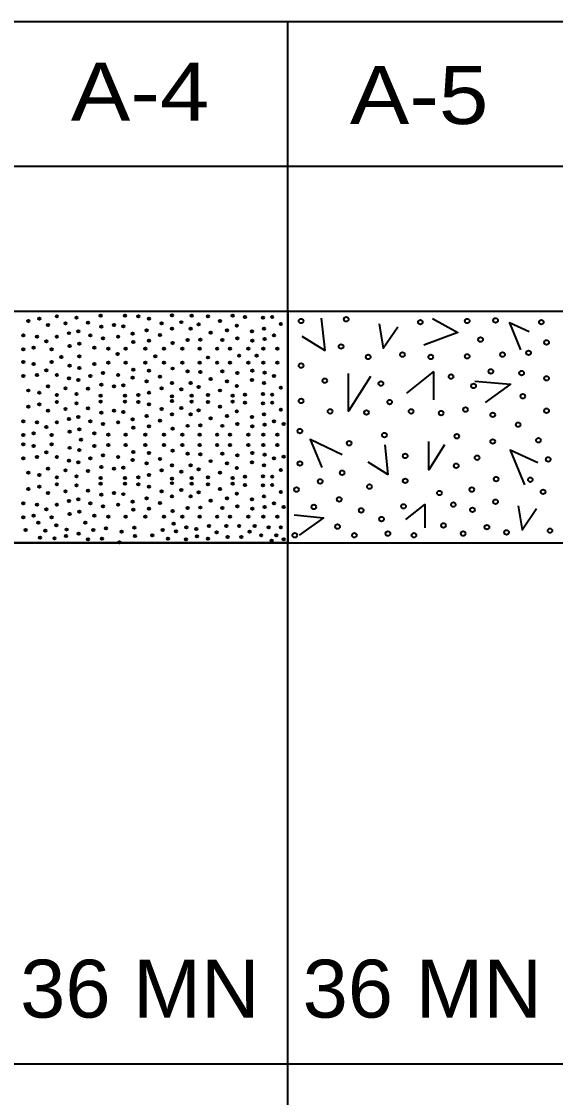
# Model space of a CAD drawing. Extents: x 2137492.6 to 2137529.1, y 2137475.8 to 2137563.
# Drawn here: x 2137497.407 to 2137498.33, y 2137553.765 to 2137555.623 of the extents above; entities that cross this region are included whole.
import ezdxf
from ezdxf.enums import TextEntityAlignment as Align

# ---------------------------------------------------------------- set-up
doc = ezdxf.new("R2010")
doc.units = 0
doc.header["$LTSCALE"] = 0.04
doc.layers.add('1', color=7, linetype='Continuous', lineweight=35)

msp = doc.modelspace()

# ---------------------------------------------------------------- linework, layer by layer
at = {"layer": '1'}
for p, q in [((2137493.171, 2137555.623), (2137501.871, 2137555.623)), ((2137497.867, 2137552.923), (2137497.867, 2137555.623)), ((2137494.121, 2137555.373), (2137499.271, 2137555.373)), ((2137493.171, 2137555.123), (2137501.871, 2137555.123)), ((2137493.171, 2137554.723), (2137501.871, 2137554.723)), ((2137493.171, 2137553.823), (2137501.871, 2137553.823))]:
    msp.add_line(p, q, dxfattribs=at)
msp.add_lwpolyline([(2137497.371, 2137555.123), (2137497.867, 2137555.123), (2137497.867, 2137554.723), (2137497.371, 2137554.723)], close=True, dxfattribs=at)
for points in [[(2137497.925, 2137555.111), (2137497.931, 2137555.055), (2137497.892, 2137555.079)], [(2137498.117, 2137555.11), (2137498.161, 2137555.086), (2137498.102, 2137555.064)], [(2137498.025, 2137555.101), (2137498.032, 2137555.059), (2137498.057, 2137555.096)], [(2137498.284, 2137555.087), (2137498.25, 2137555.103), (2137498.269, 2137555.056)], [(2137498.01, 2137555.01), (2137497.972, 2137554.95), (2137497.972, 2137555.015)], [(2137498.073, 2137554.981), (2137498.119, 2137555.018), (2137498.119, 2137554.97)], [(2137498.19, 2137555.002), (2137498.252, 2137554.997), (2137498.208, 2137554.965)], [(2137497.961, 2137554.875), (2137497.906, 2137554.901), (2137497.926, 2137554.853)], [(2137498.035, 2137554.892), (2137498.04, 2137554.841), (2137498.006, 2137554.862)], [(2137498.138, 2137554.892), (2137498.111, 2137554.849), (2137498.111, 2137554.898)], [(2137498.299, 2137554.861), (2137498.251, 2137554.883), (2137498.276, 2137554.823)], [(2137498.071, 2137554.763), (2137498.104, 2137554.789), (2137498.104, 2137554.749)], [(2137498.265, 2137554.787), (2137498.272, 2137554.745), (2137498.297, 2137554.782)], [(2137497.878, 2137554.771), (2137497.929, 2137554.766), (2137497.887, 2137554.736)]]:
    msp.add_lwpolyline(points, dxfattribs=at)
for centre, radius in [((2137497.41906, 2137555.10586), 0.002), ((2137497.43806, 2137555.10986), 0.002), ((2137497.46806, 2137555.11386), 0.002), ((2137497.50206, 2137555.11186), 0.002), ((2137497.54406, 2137555.11486), 0.002), ((2137497.58606, 2137555.11486), 0.002), ((2137497.60906, 2137555.11386), 0.002), ((2137497.62706, 2137555.10986), 0.002), ((2137497.66706, 2137555.11586), 0.002), ((2137497.68306, 2137555.10386), 0.002), ((2137497.70106, 2137555.11486), 0.002), ((2137497.72906, 2137555.11386), 0.002), ((2137497.75006, 2137555.10586), 0.002), ((2137497.77206, 2137555.11486), 0.002), ((2137497.79306, 2137555.11286), 0.002), ((2137497.82406, 2137555.11186), 0.002), ((2137497.84006, 2137555.11286), 0.002), ((2137497.89006, 2137555.10586), 0.004), ((2137497.96806, 2137555.10886), 0.004), ((2137498.09606, 2137555.10386), 0.004), ((2137498.17706, 2137555.10586), 0.004), ((2137498.22606, 2137555.10686), 0.004), ((2137498.30506, 2137555.10386), 0.004), ((2137497.45306, 2137555.09886), 0.002), ((2137497.48306, 2137555.10186), 0.002), ((2137497.50506, 2137555.08786), 0.002), ((2137497.52206, 2137555.10286), 0.002), ((2137497.54506, 2137555.09586), 0.002), ((2137497.56706, 2137555.09886), 0.002), ((2137497.58306, 2137555.09686), 0.002), ((2137497.62306, 2137555.08986), 0.002), ((2137497.64906, 2137555.10186), 0.002), ((2137497.66706, 2137555.09286), 0.002), ((2137497.69906, 2137555.09286), 0.002), ((2137497.71306, 2137555.09986), 0.002), ((2137497.73406, 2137555.08586), 0.002), ((2137497.76206, 2137555.08986), 0.002), ((2137497.77906, 2137555.09786), 0.002), ((2137497.80506, 2137555.08786), 0.002), ((2137497.82606, 2137555.09286), 0.002), ((2137497.85506, 2137555.10086), 0.002), ((2137497.41006, 2137555.08086), 0.002), ((2137497.43406, 2137555.07886), 0.002), ((2137497.45006, 2137555.07086), 0.002), ((2137497.46806, 2137555.07886), 0.002), ((2137497.48906, 2137555.08486), 0.002), ((2137497.50706, 2137555.06686), 0.002), ((2137497.52606, 2137555.08086), 0.002), ((2137497.54806, 2137555.07586), 0.002), ((2137497.57406, 2137555.07886), 0.002), ((2137497.59906, 2137555.08386), 0.002), ((2137497.60006, 2137555.06986), 0.002), ((2137497.62706, 2137555.07186), 0.002), ((2137497.64606, 2137555.08186), 0.002), ((2137497.66806, 2137555.06786), 0.002), ((2137497.69406, 2137555.07286), 0.002), ((2137497.71606, 2137555.07386), 0.002), ((2137497.75406, 2137555.07286), 0.002), ((2137497.78006, 2137555.07586), 0.002), ((2137497.80606, 2137555.07186), 0.002), ((2137497.82706, 2137555.07486), 0.002), ((2137497.84306, 2137555.08086), 0.002), ((2137498.20006, 2137555.07386), 0.004), ((2137498.31406, 2137555.06886), 0.004), ((2137497.41006, 2137555.05686), 0.002), ((2137497.42806, 2137555.05986), 0.002), ((2137497.45906, 2137555.05686), 0.002), ((2137497.49006, 2137555.06286), 0.002), ((2137497.53306, 2137555.05986), 0.002), ((2137497.55706, 2137555.05786), 0.002), ((2137497.57306, 2137555.04886), 0.002), ((2137497.58706, 2137555.05786), 0.002), ((2137497.62106, 2137555.05786), 0.002), ((2137497.65306, 2137555.05786), 0.002), ((2137497.68506, 2137555.05786), 0.002), ((2137497.71506, 2137555.05786), 0.002), ((2137497.74506, 2137555.05786), 0.002), ((2137497.76706, 2137555.05786), 0.002), ((2137497.79906, 2137555.05786), 0.002), ((2137497.82506, 2137555.05786), 0.002), ((2137497.84906, 2137555.05786), 0.002), ((2137497.95906, 2137555.06186), 0.004), ((2137498.06506, 2137555.04786), 0.004), ((2137498.23806, 2137555.04786), 0.004), ((2137498.28306, 2137555.05086), 0.004), ((2137497.41006, 2137555.03486), 0.002), ((2137497.42806, 2137555.03186), 0.002), ((2137497.45906, 2137555.03486), 0.002), ((2137497.47606, 2137555.04386), 0.002), ((2137497.50706, 2137555.04486), 0.002), ((2137497.53306, 2137555.03186), 0.002), ((2137497.55706, 2137555.03386), 0.002), ((2137497.58706, 2137555.03386), 0.002), ((2137497.62106, 2137555.03386), 0.002), ((2137497.63806, 2137555.04486), 0.002), ((2137497.65306, 2137555.03386), 0.002), ((2137497.68506, 2137555.03386), 0.002), ((2137497.71506, 2137555.03386), 0.002), ((2137497.72906, 2137555.04286), 0.002), ((2137497.74506, 2137555.03386), 0.002), ((2137497.76706, 2137555.03386), 0.002), ((2137497.78306, 2137555.04586), 0.002), ((2137497.79906, 2137555.03386), 0.002), ((2137497.81306, 2137555.04586), 0.002), ((2137497.82506, 2137555.03386), 0.002), ((2137497.84906, 2137555.03386), 0.002), ((2137497.89006, 2137555.02886), 0.004), ((2137498.00606, 2137555.04386), 0.004), ((2137498.11406, 2137555.04386), 0.004), ((2137498.17706, 2137555.04486), 0.004), ((2137497.41006, 2137555.01086), 0.002), ((2137497.43406, 2137555.01286), 0.002), ((2137497.45006, 2137555.02086), 0.002), ((2137497.46806, 2137555.01286), 0.002), ((2137497.49006, 2137555.02886), 0.002), ((2137497.50706, 2137555.02486), 0.002), ((2137497.52606, 2137555.01086), 0.002), ((2137497.54806, 2137555.01586), 0.002), ((2137497.57406, 2137555.01286), 0.002), ((2137497.60006, 2137555.02186), 0.002), ((2137497.62706, 2137555.01986), 0.002), ((2137497.66806, 2137555.02386), 0.002), ((2137497.69406, 2137555.01886), 0.002), ((2137497.71606, 2137555.01786), 0.002), ((2137497.75406, 2137555.01886), 0.002), ((2137497.78006, 2137555.01586), 0.002), ((2137497.80606, 2137555.01986), 0.002), ((2137497.82706, 2137555.01686), 0.002), ((2137497.84306, 2137555.01086), 0.002), ((2137498.14906, 2137555.00986), 0.004), ((2137498.21806, 2137555.01886), 0.004), ((2137498.27106, 2137555.01586), 0.004), ((2137497.45306, 2137554.99286), 0.002), ((2137497.48906, 2137555.00686), 0.002), ((2137497.50506, 2137555.00386), 0.002), ((2137497.54506, 2137554.99586), 0.002), ((2137497.56706, 2137554.99286), 0.002), ((2137497.58306, 2137554.99486), 0.002), ((2137497.59906, 2137555.00786), 0.002), ((2137497.62306, 2137555.00186), 0.002), ((2137497.64606, 2137555.00986), 0.002), ((2137497.66706, 2137554.99886), 0.002), ((2137497.69906, 2137554.99886), 0.002), ((2137497.73406, 2137555.00586), 0.002), ((2137497.76206, 2137555.00186), 0.002), ((2137497.77906, 2137554.99386), 0.002), ((2137497.80506, 2137555.00386), 0.002), ((2137497.82606, 2137554.99886), 0.002), ((2137497.93106, 2137555.00286), 0.004), ((2137498.02806, 2137554.99786), 0.004), ((2137498.18806, 2137554.99386), 0.004), ((2137498.31406, 2137555.00686), 0.004), ((2137497.41906, 2137554.98586), 0.002), ((2137497.43806, 2137554.98186), 0.002), ((2137497.46806, 2137554.97786), 0.002), ((2137497.48306, 2137554.98986), 0.002), ((2137497.50206, 2137554.97986), 0.002), ((2137497.52206, 2137554.98886), 0.002), ((2137497.54406, 2137554.97686), 0.002), ((2137497.58606, 2137554.97686), 0.002), ((2137497.60906, 2137554.97786), 0.002), ((2137497.62706, 2137554.98186), 0.002), ((2137497.64906, 2137554.98986), 0.002), ((2137497.66706, 2137554.97586), 0.002), ((2137497.68306, 2137554.98786), 0.002), ((2137497.70106, 2137554.97686), 0.002), ((2137497.71306, 2137554.99186), 0.002), ((2137497.72906, 2137554.97786), 0.002), ((2137497.75006, 2137554.98586), 0.002), ((2137497.77206, 2137554.97686), 0.002), ((2137497.79306, 2137554.97886), 0.002), ((2137497.82406, 2137554.97986), 0.002), ((2137497.84006, 2137554.97886), 0.002), ((2137497.85506, 2137554.99086), 0.002), ((2137498.27306, 2137554.97586), 0.004), ((2137497.41906, 2137554.95786), 0.002), ((2137497.43806, 2137554.96186), 0.002), ((2137497.46806, 2137554.96586), 0.002), ((2137497.50206, 2137554.96386), 0.002), ((2137497.54406, 2137554.96686), 0.002), ((2137497.58606, 2137554.96686), 0.002), ((2137497.60906, 2137554.96586), 0.002), ((2137497.62706, 2137554.96186), 0.002), ((2137497.66706, 2137554.96786), 0.002), ((2137497.68306, 2137554.95586), 0.002), ((2137497.70106, 2137554.96686), 0.002), ((2137497.72906, 2137554.96586), 0.002), ((2137497.75006, 2137554.95786), 0.002), ((2137497.77206, 2137554.96686), 0.002), ((2137497.79306, 2137554.96486), 0.002), ((2137497.82406, 2137554.96386), 0.002), ((2137497.84006, 2137554.96486), 0.002), ((2137497.89006, 2137554.96786), 0.004), ((2137498.04306, 2137554.96586), 0.004), ((2137497.45306, 2137554.95086), 0.002), ((2137497.48306, 2137554.95386), 0.002), ((2137497.48906, 2137554.93686), 0.002), ((2137497.50506, 2137554.93986), 0.002), ((2137497.52206, 2137554.95486), 0.002), ((2137497.54506, 2137554.94786), 0.002), ((2137497.56706, 2137554.95086), 0.002), ((2137497.58306, 2137554.94886), 0.002), ((2137497.62306, 2137554.94186), 0.002), ((2137497.64906, 2137554.95386), 0.002), ((2137497.66706, 2137554.94486), 0.002), ((2137497.69906, 2137554.94486), 0.002), ((2137497.71306, 2137554.95186), 0.002), ((2137497.73406, 2137554.93786), 0.002), ((2137497.76206, 2137554.94186), 0.002), ((2137497.77906, 2137554.94986), 0.002), ((2137497.80506, 2137554.93986), 0.002), ((2137497.82606, 2137554.94486), 0.002), ((2137497.85506, 2137554.95286), 0.002), ((2137497.94006, 2137554.94986), 0.004), ((2137498.00306, 2137554.94786), 0.004), ((2137498.08006, 2137554.94986), 0.004), ((2137498.13206, 2137554.94686), 0.004), ((2137498.17406, 2137554.95286), 0.004), ((2137498.22106, 2137554.94386), 0.004), ((2137498.31406, 2137554.95086), 0.004), ((2137497.41006, 2137554.93286), 0.002), ((2137497.43406, 2137554.93086), 0.002), ((2137497.45006, 2137554.92286), 0.002), ((2137497.46806, 2137554.93086), 0.002), ((2137497.50706, 2137554.91886), 0.002), ((2137497.52606, 2137554.93286), 0.002), ((2137497.54806, 2137554.92786), 0.002), ((2137497.57406, 2137554.93086), 0.002), ((2137497.59906, 2137554.93586), 0.002), ((2137497.60006, 2137554.92186), 0.002), ((2137497.62706, 2137554.92386), 0.002), ((2137497.64606, 2137554.93386), 0.002), ((2137497.66806, 2137554.91986), 0.002), ((2137497.69406, 2137554.92486), 0.002), ((2137497.71606, 2137554.92586), 0.002), ((2137497.75406, 2137554.92486), 0.002), ((2137497.78006, 2137554.92786), 0.002), ((2137497.80606, 2137554.92386), 0.002), ((2137497.82706, 2137554.92686), 0.002), ((2137497.84306, 2137554.93286), 0.002), ((2137497.86006, 2137554.92786), 0.002), ((2137498.26506, 2137554.92686), 0.004), ((2137497.41006, 2137554.90886), 0.002), ((2137497.42806, 2137554.91186), 0.002), ((2137497.45906, 2137554.90886), 0.002), ((2137497.49006, 2137554.91486), 0.002), ((2137497.51006, 2137554.90086), 0.002), ((2137497.53306, 2137554.91186), 0.002), ((2137497.55706, 2137554.90986), 0.002), ((2137497.58706, 2137554.90986), 0.002), ((2137497.62106, 2137554.90986), 0.002), ((2137497.65306, 2137554.90986), 0.002), ((2137497.68506, 2137554.90986), 0.002), ((2137497.71506, 2137554.90986), 0.002), ((2137497.74506, 2137554.90986), 0.002), ((2137497.76706, 2137554.90986), 0.002), ((2137497.79906, 2137554.90986), 0.002), ((2137497.82506, 2137554.90986), 0.002), ((2137497.84906, 2137554.90986), 0.002), ((2137497.88806, 2137554.91586), 0.004), ((2137498.03406, 2137554.90886), 0.004), ((2137498.15906, 2137554.90686), 0.004), ((2137498.22106, 2137554.89786), 0.004), ((2137498.30006, 2137554.89986), 0.004), ((2137497.41006, 2137554.89286), 0.002), ((2137497.42806, 2137554.88986), 0.002), ((2137497.45906, 2137554.89286), 0.002), ((2137497.49006, 2137554.88686), 0.002), ((2137497.50706, 2137554.88286), 0.002), ((2137497.53306, 2137554.88986), 0.002), ((2137497.55706, 2137554.89186), 0.002), ((2137497.58706, 2137554.89186), 0.002), ((2137497.62106, 2137554.89186), 0.002), ((2137497.65306, 2137554.89186), 0.002), ((2137497.66806, 2137554.88186), 0.002), ((2137497.68506, 2137554.89186), 0.002), ((2137497.71506, 2137554.89186), 0.002), ((2137497.74506, 2137554.89186), 0.002), ((2137497.76706, 2137554.89186), 0.002), ((2137497.79906, 2137554.89186), 0.002), ((2137497.82506, 2137554.89186), 0.002), ((2137497.84906, 2137554.89186), 0.002), ((2137497.97306, 2137554.89486), 0.004), ((2137497.41006, 2137554.86886), 0.002), ((2137497.43406, 2137554.87086), 0.002), ((2137497.45006, 2137554.87886), 0.002), ((2137497.46806, 2137554.87086), 0.002), ((2137497.48906, 2137554.86486), 0.002), ((2137497.52606, 2137554.86886), 0.002), ((2137497.54806, 2137554.87386), 0.002), ((2137497.57406, 2137554.87086), 0.002), ((2137497.59906, 2137554.86586), 0.002), ((2137497.60006, 2137554.87986), 0.002), ((2137497.62706, 2137554.87786), 0.002), ((2137497.64606, 2137554.86786), 0.002), ((2137497.69406, 2137554.87686), 0.002), ((2137497.71606, 2137554.87586), 0.002), ((2137497.73406, 2137554.86386), 0.002), ((2137497.75406, 2137554.87686), 0.002), ((2137497.78006, 2137554.87386), 0.002), ((2137497.80606, 2137554.87786), 0.002), ((2137497.82706, 2137554.87486), 0.002), ((2137497.84306, 2137554.86886), 0.002), ((2137497.86006, 2137554.87186), 0.002), ((2137498.07006, 2137554.87286), 0.004), ((2137498.19406, 2137554.86986), 0.004), ((2137498.31706, 2137554.86686), 0.004), ((2137497.41906, 2137554.84386), 0.002), ((2137497.45306, 2137554.85086), 0.002), ((2137497.48306, 2137554.84786), 0.002), ((2137497.50506, 2137554.86186), 0.002), ((2137497.52206, 2137554.84686), 0.002), ((2137497.54506, 2137554.85386), 0.002), ((2137497.56706, 2137554.85086), 0.002), ((2137497.58306, 2137554.85286), 0.002), ((2137497.62306, 2137554.85986), 0.002), ((2137497.64906, 2137554.84786), 0.002), ((2137497.66706, 2137554.85686), 0.002), ((2137497.68306, 2137554.84586), 0.002), ((2137497.69906, 2137554.85686), 0.002), ((2137497.71306, 2137554.84986), 0.002), ((2137497.75006, 2137554.84386), 0.002), ((2137497.76206, 2137554.85986), 0.002), ((2137497.77906, 2137554.85186), 0.002), ((2137497.80506, 2137554.86186), 0.002), ((2137497.82606, 2137554.85686), 0.002), ((2137497.85506, 2137554.84886), 0.002), ((2137497.88806, 2137554.85986), 0.004), ((2137497.96106, 2137554.84386), 0.004), ((2137498.15806, 2137554.85586), 0.004), ((2137497.43806, 2137554.83986), 0.002), ((2137497.46806, 2137554.83586), 0.002), ((2137497.50206, 2137554.83786), 0.002), ((2137497.54406, 2137554.83486), 0.002), ((2137497.58606, 2137554.83486), 0.002), ((2137497.60906, 2137554.83586), 0.002), ((2137497.62706, 2137554.83986), 0.002), ((2137497.66706, 2137554.83386), 0.002), ((2137497.66706, 2137554.82586), 0.002), ((2137497.70106, 2137554.83486), 0.002), ((2137497.72906, 2137554.83586), 0.002), ((2137497.77206, 2137554.83486), 0.002), ((2137497.79306, 2137554.83686), 0.002), ((2137497.82406, 2137554.83786), 0.002), ((2137497.84006, 2137554.83686), 0.002), ((2137497.92306, 2137554.82886), 0.004), ((2137498.07006, 2137554.82986), 0.004), ((2137498.22706, 2137554.83286), 0.004), ((2137498.28606, 2137554.83186), 0.004), ((2137497.41906, 2137554.81586), 0.002), ((2137497.43806, 2137554.81986), 0.002), ((2137497.45306, 2137554.80886), 0.002), ((2137497.46806, 2137554.82386), 0.002), ((2137497.48306, 2137554.81186), 0.002), ((2137497.50206, 2137554.82186), 0.002), ((2137497.52206, 2137554.81286), 0.002), ((2137497.54406, 2137554.82486), 0.002), ((2137497.56706, 2137554.80886), 0.002), ((2137497.58306, 2137554.80686), 0.002), ((2137497.58606, 2137554.82486), 0.002), ((2137497.60906, 2137554.82386), 0.002), ((2137497.62706, 2137554.81986), 0.002), ((2137497.64906, 2137554.81186), 0.002), ((2137497.68306, 2137554.81386), 0.002), ((2137497.70106, 2137554.82486), 0.002), ((2137497.71306, 2137554.80986), 0.002), ((2137497.72906, 2137554.82386), 0.002), ((2137497.75006, 2137554.81586), 0.002), ((2137497.77206, 2137554.82486), 0.002), ((2137497.77906, 2137554.80786), 0.002), ((2137497.79306, 2137554.82286), 0.002), ((2137497.82406, 2137554.82186), 0.002), ((2137497.84006, 2137554.82286), 0.002), ((2137497.85506, 2137554.81086), 0.002), ((2137497.88206, 2137554.81486), 0.004), ((2137498.00806, 2137554.81986), 0.004), ((2137498.12906, 2137554.80886), 0.004), ((2137498.18506, 2137554.81486), 0.004), ((2137498.30806, 2137554.81086), 0.004), ((2137497.41006, 2137554.79086), 0.002), ((2137497.43406, 2137554.78886), 0.002), ((2137497.46806, 2137554.78886), 0.002), ((2137497.48906, 2137554.79486), 0.002), ((2137497.50506, 2137554.79786), 0.002), ((2137497.52606, 2137554.79086), 0.002), ((2137497.54506, 2137554.80586), 0.002), ((2137497.57406, 2137554.78886), 0.002), ((2137497.59906, 2137554.79386), 0.002), ((2137497.62306, 2137554.79986), 0.002), ((2137497.64606, 2137554.79186), 0.002), ((2137497.66706, 2137554.80286), 0.002), ((2137497.69906, 2137554.80286), 0.002), ((2137497.73406, 2137554.79586), 0.002), ((2137497.76206, 2137554.79986), 0.002), ((2137497.80506, 2137554.79786), 0.002), ((2137497.82606, 2137554.80286), 0.002), ((2137497.84306, 2137554.79086), 0.002), ((2137497.95606, 2137554.79786), 0.004), ((2137498.15306, 2137554.78886), 0.004), ((2137498.22606, 2137554.79386), 0.004), ((2137497.42806, 2137554.76986), 0.002), ((2137497.45006, 2137554.78086), 0.002), ((2137497.49006, 2137554.77286), 0.002), ((2137497.50706, 2137554.77686), 0.002), ((2137497.53306, 2137554.76986), 0.002), ((2137497.54806, 2137554.78586), 0.002), ((2137497.60006, 2137554.77986), 0.002), ((2137497.62706, 2137554.78186), 0.002), ((2137497.66806, 2137554.77786), 0.002), ((2137497.69406, 2137554.78286), 0.002), ((2137497.71606, 2137554.78386), 0.002), ((2137497.75406, 2137554.78286), 0.002), ((2137497.78006, 2137554.78586), 0.002), ((2137497.80606, 2137554.78186), 0.002), ((2137497.82706, 2137554.78486), 0.002), ((2137497.86006, 2137554.78486), 0.002), ((2137497.91206, 2137554.78486), 0.004), ((2137497.99406, 2137554.77886), 0.004), ((2137498.06706, 2137554.78586), 0.004), ((2137498.18606, 2137554.77986), 0.004), ((2137497.41006, 2137554.76686), 0.002), ((2137497.43606, 2137554.75786), 0.002), ((2137497.45906, 2137554.76686), 0.002), ((2137497.46706, 2137554.75286), 0.002), ((2137497.51706, 2137554.75786), 0.002), ((2137497.55706, 2137554.76786), 0.002), ((2137497.58706, 2137554.76786), 0.002), ((2137497.62106, 2137554.76786), 0.002), ((2137497.65306, 2137554.76786), 0.002), ((2137497.67006, 2137554.75586), 0.002), ((2137497.68506, 2137554.76786), 0.002), ((2137497.71506, 2137554.76786), 0.002), ((2137497.73106, 2137554.75186), 0.002), ((2137497.74506, 2137554.76786), 0.002), ((2137497.76106, 2137554.75186), 0.002), ((2137497.76706, 2137554.76786), 0.002), ((2137497.78306, 2137554.75186), 0.002), ((2137497.79906, 2137554.76786), 0.002), ((2137497.81006, 2137554.75186), 0.002), ((2137497.82506, 2137554.76786), 0.002), ((2137497.84906, 2137554.76786), 0.002), ((2137497.95306, 2137554.75086), 0.004), ((2137498.02906, 2137554.76386), 0.004), ((2137498.13606, 2137554.75286), 0.004), ((2137498.21106, 2137554.74986), 0.004), ((2137497.41406, 2137554.74486), 0.002), ((2137497.44806, 2137554.74386), 0.002), ((2137497.48406, 2137554.73486), 0.002), ((2137497.48506, 2137554.74586), 0.002), ((2137497.50606, 2137554.73886), 0.002), ((2137497.53106, 2137554.74486), 0.002), ((2137497.55306, 2137554.74786), 0.002), ((2137497.58006, 2137554.74186), 0.002), ((2137497.60206, 2137554.74886), 0.002), ((2137497.60306, 2137554.73486), 0.002), ((2137497.63306, 2137554.73586), 0.002), ((2137497.65106, 2137554.74486), 0.002), ((2137497.67406, 2137554.74286), 0.002), ((2137497.69206, 2137554.74986), 0.002), ((2137497.70906, 2137554.74686), 0.002), ((2137497.71006, 2137554.73386), 0.002), ((2137497.74406, 2137554.74086), 0.002), ((2137497.76306, 2137554.73286), 0.002), ((2137497.78706, 2137554.73286), 0.002), ((2137497.80106, 2137554.74186), 0.002), ((2137497.82106, 2137554.73586), 0.002), ((2137497.83406, 2137554.74986), 0.002), ((2137497.84706, 2137554.73586), 0.002), ((2137497.85506, 2137554.74986), 0.002), ((2137497.87906, 2137554.73586), 0.004), ((2137497.98206, 2137554.73586), 0.004), ((2137498.04006, 2137554.73886), 0.004), ((2137498.08506, 2137554.73586), 0.004), ((2137498.17006, 2137554.73886), 0.004), ((2137498.24506, 2137554.74086), 0.004), ((2137498.32006, 2137554.74386), 0.004), ((2137497.43906, 2137554.73186), 0.002), ((2137497.46406, 2137554.73086), 0.002), ((2137497.52206, 2137554.72886), 0.002), ((2137497.54606, 2137554.72986), 0.002), ((2137497.57606, 2137554.72386), 0.002), ((2137497.66006, 2137554.72986), 0.002), ((2137497.69106, 2137554.72886), 0.002), ((2137497.72906, 2137554.72986), 0.002), ((2137497.83906, 2137554.72686), 0.002), ((2137497.86006, 2137554.72886), 0.002)]:
    msp.add_circle(centre, radius, dxfattribs=at)

# ---------------------------------------------------------------- texts
for s, width, p in [('A-4', 1.15, (2137497.612, 2137555.452)), ('A-5', 1.15, (2137498.094, 2137555.446)), ('36 MN', 1.05, (2137497.6115, 2137553.903)), ('36 MN', 1.05, (2137498.0995, 2137553.903))]:
    msp.add_text(s, height=0.1, dxfattribs=dict(at, width=width)).set_placement(p, align=Align.CENTER)

doc.saveas('drawing.dxf')
